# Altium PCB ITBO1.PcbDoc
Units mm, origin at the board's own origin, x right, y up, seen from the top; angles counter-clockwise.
Board outline 85 x 45 mm, 2 copper layers (Top Layer, Bottom Layer); 68 components, 43 nets, 200 pads, 0 vias.
Unrouted connection lines stored in the file: 118.
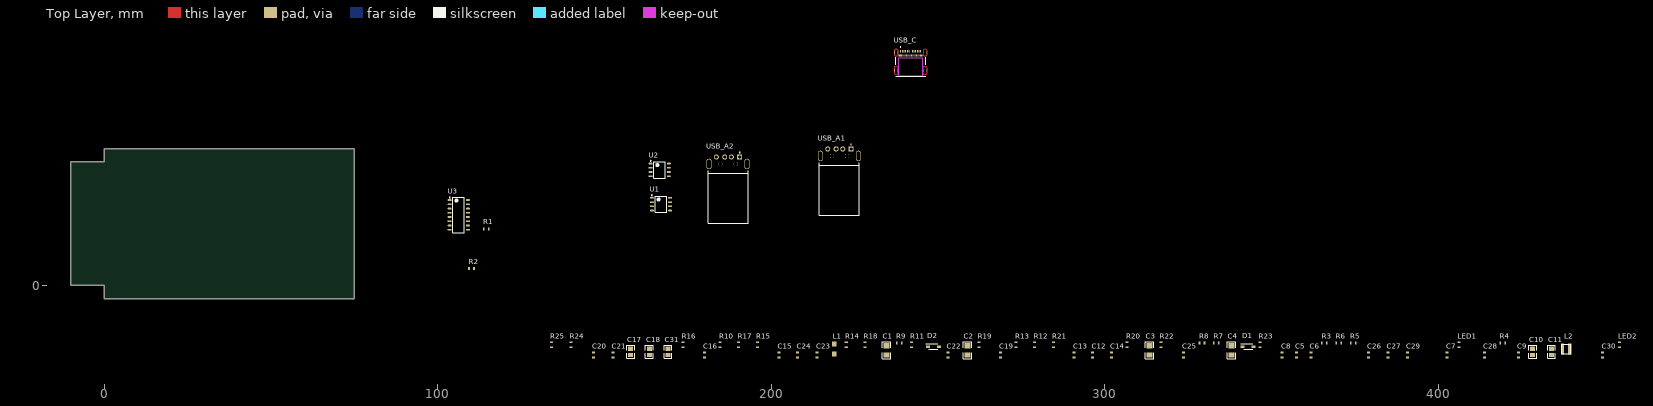
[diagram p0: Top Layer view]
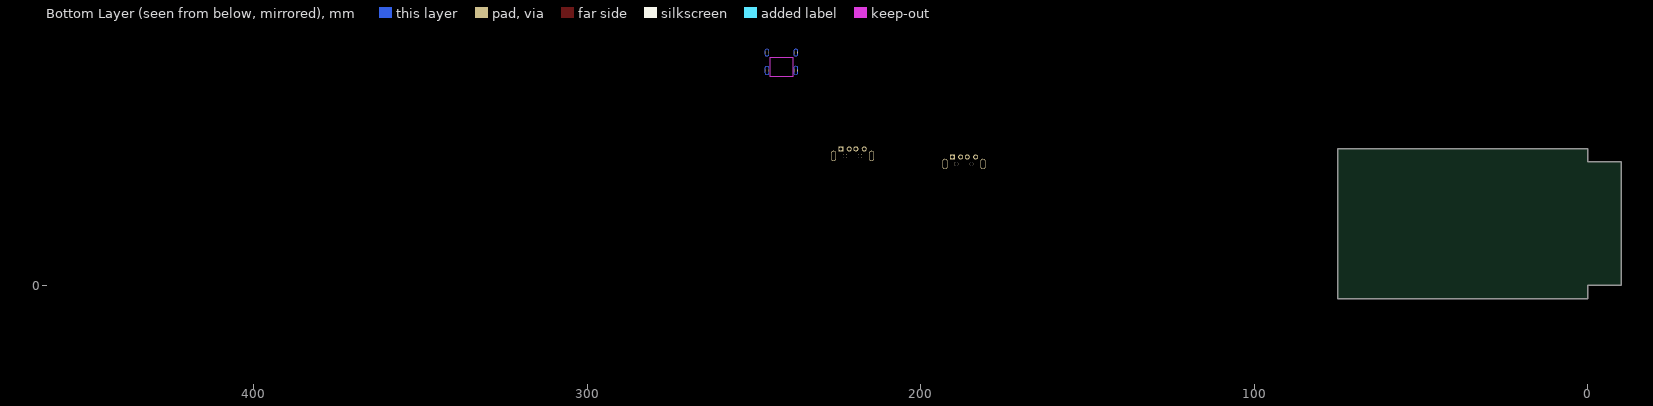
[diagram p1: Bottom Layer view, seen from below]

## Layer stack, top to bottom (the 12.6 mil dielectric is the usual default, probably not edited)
Top Solder: solder mask 0.0102, Solder Resist, Dk 3.5
Top Layer: signal copper 0.0356
Dielectric 1: dielectric 0.32, FR-4, Dk 4.8
Bottom Layer: signal copper 0.0356
Bottom Solder: solder mask 0.0102, Solder Resist, Dk 3.5

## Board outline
0,0 -10,0 -10,37 0,37 0,41 75,41 75,-4 0,-4

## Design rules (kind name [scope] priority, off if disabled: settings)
Clearance [All] p1: gap=0.254 ignorepadtopadclearanceinfootprint=FALSE except(0: Arc-Hole Track-Hole SMDPad-Hole THPad-Hole Via-Hole Fill-Hole Poly-Hole Region-Hole Text-Hole)
PolygonConnect [All] p1: connectstyle=Relief reliefconductorwidth=0.254 reliefentries=4 polygonreliefangle="90 Angle" airgapwidth=0.254
RoomDefinition ITBO1 [InComponentClass('ITBO1')] p1: confinementstyle=ConfineIn formatcopy=TRUE lockcomponents=FALSE outline 125.345,-47.575 459.992,-47.575 459.992,94.03 125.345,94.03
RoutingVias [All] p1: holewidth=0.711 width=1.27 viastyle="Through Hole" minholewidth=0.711 minwidth=1.27 maxholewidth=0.711 maxwidth=1.27
SolderMaskExpansion [All] p1: expansion=0.102 istentingtop=FALSE
Width [All] p1: maxlimit=0.254 minlimit=0.254 preferedwidth=0.254
30 further rules are at their usual default settings.

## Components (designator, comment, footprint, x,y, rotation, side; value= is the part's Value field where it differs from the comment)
C1 "375n" 1206 234.567,-20.88 r90 top
C2 "375n" 1206 258.824,-20.88 r90 top
C3 "375n" 1206 313.434,-20.88 r90 top
C4 "375n" 1206 338.072,-20.88 r90 top
C5 "33u" "0603 - R" 357.503,-20.88 r90 top
C6 "33u" "0603 - R" 361.821,-20.88 r90 top
C7 "" "0603 - R" 402.715,-20.88 r90 top
C8 "11.67u" "0603 - R" 353.185,-20.88 r90 top
C9 "13.83u" "0603 - R" 424.051,-20.88 r90 top
C10 "13.75u" 0805 428.369,-20.88 r90 top
C11 "13.73u" 0805 433.957,-20.88 r90 top
C12 "4.82n" "0603 - R" 296.416,-20.88 r90 top
C13 "1.14n" "0603 - R" 290.828,-20.88 r90 top
C14 "866p" "0603 - R" 302.004,-20.88 r90 top
C15 "9.41n" "0603 - R" 202.309,-20.88 r90 top
C16 "41.84n" "0603 - R" 179.957,-20.88 r90 top
C17 "33u" 0805 157.859,-20.88 r90 top
C18 "33u" 0805 163.447,-20.88 r90 top
C19 "9.65n" "0603 - R" 268.73,-20.88 r90 top
C20 "9.5n" "0603 - R" 146.683,-20.88 r90 top
C21 "734p" "0603 - R" 152.525,-20.88 r90 top
C22 "85n" "0603 - R" 252.982,-20.88 r90 top
C23 "7.67u" "0603 - R" 213.739,-20.88 r90 top
C24 "7.67u" "0603 - R" 207.897,-20.88 r90 top
C25 "0.97n" "0603 - R" 323.594,-20.88 r90 top
C26 "42.38n" "0603 - R" 379.093,-20.88 r90 top
C27 "42.38n" "0603 - R" 384.935,-20.88 r90 top
C28 "9.92n" "0603 - R" 413.891,-20.88 r90 top
C29 "42n" "0603 - R" 390.777,-20.88 r90 top
C30 "7.68u" "0603 - R" 449.324,-20.88 r90 top
C31 "33u" 0805 169.035,-20.88 r90 top
D1 "1N4148W-7-F" DIODES_SOD123_2_H 343.025,-18.34 r0 top
D2 "1N4148W-7-F" DIODES_SOD123_2_H 248.664,-18.34 r0 top
L1 "L" "1806 - R" 218.946,-19.102 r90 top value=6.716u
L2 "10.5u" WE-TPC 438.402,-19.102 r90 top
LED1 "tbd" "LED-RED-0603[1608]  - RFL" 406.271,-17.832 r90 top value=RED
LED2 "tbd" "LED-BLUE-0603[1608]  - RFL" 454.404,-17.832 r90 top value=BLUE
R1 "4.7" "0603 - R" 114.562,16.941 r0 top value=1k
R2 "4.7" "0603 - R" 110.105,5.003 r0 top value=1k
R3 "47k" "0603 - R" 365.885,-17.324 r0 top value=47k5
R4 "110k" "0603 - R" 419.352,-17.324 r0 top
R5 "57k6" "0603 - R" 374.521,-17.324 r0 top
R6 "4.7" "0603 - R" 370.203,-17.324 r0 top
R7 "224k" "0603 - R" 333.5,-17.324 r0 top
R8 "2k22" "0603 - R" 329.182,-17.324 r0 top
R9 "112k" "0603 - R" 238.377,-17.324 r0 top
R10 "112k" "0603 - R" 184.656,-17.832 r90 top
R11 "47.3k" "0603 - R" 242.06,-17.832 r90 top
R12 "4k72" "0603 - R" 279.017,-17.832 r90 top
R13 "33k3" "0603 - R" 273.429,-17.832 r90 top
R14 "2meg7" "0603 - R" 222.502,-17.832 r90 top
R15 "22k3" "0603 - R" 195.832,-17.832 r90 top
R16 "100k" "0603 - R" 173.48,-17.832 r90 top
R17 "22k3" "0603 - R" 190.244,-17.832 r90 top
R18 "1K" "0603 - R" 228.09,-17.832 r90 top
R19 "2k22" "0603 - R" 262.253,-17.832 r90 top
R20 "1K" "0603 - R" 306.703,-17.832 r90 top
R21 "1K" "0603 - R" 284.605,-17.832 r90 top
R22 "7k" "0603 - R" 316.863,-17.832 r90 top
R23 "7k" "0603 - R" 346.581,-17.832 r90 top
R24 "3k32" "0603 - R" 139.952,-17.832 r90 top
R25 "22k3" "0603 - R" 134.11,-17.832 r90 top
U1 "ITBO1_U1" ITBO1_U1 166.934,24.332 r0 top
U2 "ITBO1_U2" ITBO1_U2 166.553,34.619 r0 top
U3 "ITBO1_U3" ITBO1_U3 106.295,21.132 r0 top
USB_A1 "ITBO_USB_A1" MOLEX_48037-0001 220.455,38.81 r0 top
USB_A2 "ITBO_USB_A2" MOLEX_48037-0001 187.054,36.397 r0 top
USB_C "ITBO_USB_C" MOLEX_105450-0101 241.802,66.439 r0 top

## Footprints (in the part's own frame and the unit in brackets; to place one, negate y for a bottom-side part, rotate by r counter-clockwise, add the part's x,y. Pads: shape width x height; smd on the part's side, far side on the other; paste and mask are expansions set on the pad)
"0603 - R" [mm] "SMD Chip 0603 - Reflow"
  rect 0.5x0.9 smd: 1(-0.75,0) 2(0.75,0)
0805 [mm] "SMD Chip 0805"
  rect 1.3x1.5 smd: 1(0,0) 2(1.9,0)
  silkscreen extent -1.05,-1.15 2.95,1.15
1206 [mm] "SMD Chip 1206"
  rect 1.6x1.8 smd: 1(0,0) 2(2.8,0)
  silkscreen extent -1.2,-1.3 4,1.3
"1806 - R" [mm] "Body 5 x 2 mm (LxW typ)"
  rect 1.5x1.35 smd: 1(-1.5,0) 2(1.5,0)
DIODES_SOD123_2_H [mm] "DIODES_SOD123_2_H"
  rect 1.25x0.75 smd: 1(-1.65,0) 2(1.65,0)
  silkscreen extent -2.27,-0.8 1.35,0.8, body extent -1.42,-0.85 1.43,0.85, height 1.35
ITBO1_U1 [mm] "TSOP, 8-Leads, Body 4.85x3.85mm, Pitch 1.27mm, IPC Medium Density"
  oval 1.2x0.5 smd: 1(-2.725,1.905) 2(-2.725,0.635) 3(-2.725,-0.635) 4(-2.725,-1.905) 5(2.725,-1.905) 6(2.725,-0.635) 7(2.725,0.635) 8(2.725,1.905)
  silkscreen extent -2.85,-2.45 1.73,2.83, body extent -2.93,-2.45 2.93,2.45, height 1.25
ITBO1_U2 [mm] "TSOP, 8-Leads, Body 4.85x3.85mm, Pitch 1.27mm, IPC Medium Density"
  oval 1.2x0.5 smd: 1(-2.725,1.905) 2(-2.725,0.635) 3(-2.725,-0.635) 4(-2.725,-1.905) 5(2.725,-1.905) 6(2.725,-0.635) 7(2.725,0.635) 8(2.725,1.905)
  silkscreen extent -2.85,-2.45 1.73,2.83, body extent -2.93,-2.45 2.93,2.45, height 1.25
ITBO1_U3 [mm]
  oval 1.2x0.5 smd: 1(-2.725,4.445) 2(-2.725,3.175) 3(-2.725,1.905) 4(-2.725,0.635) 5(-2.725,-0.635) 6(-2.725,-1.905) 7(-2.725,-3.175) 8(-2.725,-4.445) 9(2.725,-4.445) 10(2.725,-3.175) 11(2.725,-1.905) 12(2.725,-0.635) 13(2.725,0.635) 14(2.725,1.905) 15(2.725,3.175) 16(2.725,4.445)
  silkscreen extent -2.85,-5.3 1.73,5.37, body extent -2.93,-5.3 2.93,5.3, height 1.25
"LED-BLUE-0603[1608]  - RFL" [mm] "SMD Chip 0603 - LED BLUE - RFL"
  rect 0.5x0.9 smd: 1(-0.75,0) 2(0.75,0)
  body extent -0.85,-0.42 0.77,0.38, height 0.6
"LED-RED-0603[1608]  - RFL" [mm] "SMD Chip 0603 - LED RED - RFL"
  rect 0.5x0.9 smd: 1(-0.75,0) 2(0.75,0)
  body extent -0.85,-0.42 0.77,0.38, height 0.6
MOLEX_48037-0001 [mm]
  rect 1.508x1.508 hole 1: 1(3.5,2.1)
  round 1.508 hole 1: 2(1,2.1) 3(-1,2.1) 4(-3.5,2.1)
  oval 1.575x3.15 hole 1.05 slot 2.6 at 90 deg: S1(5.7,0) S2(-5.7,0)
  round 1.25 hole 1.25 unplated: ""(-2.25,0) ""(2.25,0)
  silkscreen extent -6,-17.8 6,3.5
MOLEX_105450-0101 [mm]
  rect 0.3x0.7 smd: A1(-3,3.77) A2(-2.5,3.77) A3(-2,3.77) A4(-1.5,3.77) A5(-1,3.77) A6(-0.5,3.77) A7(0.5,3.77) A8(1,3.77) A9(1.5,3.77) A10(2,3.77) A11(2.5,3.77) A12(3,3.77) B2(2.25,2.47) B3(1.75,2.47) B4(1.25,2.47) B5(0.75,2.47) B6(0.25,2.47) B7(-0.25,2.47) B8(-0.75,2.47) B9(-1.25,2.47) B10(-1.75,2.47) B11(-2.25,2.47)
  rect 1x0.7 smd: B1(3.1,2.47) B12(-3.1,2.47)
  round 1.2 hole 0.65 slot 1.7 at 90 deg mask+0: S1(-4.32,3.36)
  round 1.2 hole 0.65 slot 1.725 at 90 deg mask+0: S2(4.32,3.36)
  round 1.2 hole 0.65 slot 2.175 at 90 deg mask+0: S3(-4.32,-2) S4(4.32,-2)
  Top Layer region: 4.35,-0.702 4.382,-0.706 4.414,-0.711 4.446,-0.718 4.478,-0.727 4.509,-0.737 4.539,-0.749 4.569,-0.763 4.598,-0.778 4.626,-0.795 4.654,-0.813 4.68,-0.832 4.705,-0.853 4.73,-0.875 4.752,-0.898 4.774,-0.923 4.795,-0.949 4.814,-0.975 4.831,-1.003 4.847,-1.031 4.862,-1.061 4.875,-1.091 4.886,-1.121 4.896,-1.153 4.904,-1.184 4.911,-1.216 4.916,-1.249 4.919,-1.281 4.92,-1.314 4.92,-1.35 4.92,-2.65 4.92,-2.686 4.919,-2.719 4.916,-2.751 4.911,-2.784 4.904,-2.816 4.896,-2.847 4.886,-2.879 4.875,-2.909 4.862,-2.939 4.847,-2.969 4.831,-2.997 4.814,-3.025 4.795,-3.051 4.774,-3.077 4.752,-3.102 4.73,-3.125 4.705,-3.147 4.68,-3.168 4.654,-3.187 4.626,-3.205 4.598,-3.222 4.569,-3.237 4.539,-3.251 4.509,-3.263 4.478,-3.273 4.446,-3.282 4.414,-3.289 4.382,-3.294 4.35,-3.298 4.32,-3.3 4.29,-3.298 4.258,-3.294 4.226,-3.289 4.194,-3.282 4.162,-3.273 4.131,-3.263 4.101,-3.251 4.071,-3.237 4.042,-3.222 4.014,-3.205 3.986,-3.187 3.96,-3.168 3.935,-3.147 3.91,-3.125 3.888,-3.102 3.866,-3.077 3.845,-3.051 3.826,-3.025 3.809,-2.997 3.793,-2.969 3.778,-2.939 3.765,-2.909 3.754,-2.879 3.744,-2.847 3.736,-2.816 3.729,-2.784 3.724,-2.751 3.721,-2.719 3.72,-2.686 3.72,-2.65 3.72,-1.35 3.72,-1.314 3.721,-1.281 3.724,-1.249 3.729,-1.216 3.736,-1.184 3.744,-1.153 3.754,-1.121 3.765,-1.091 3.778,-1.061 3.793,-1.031 3.809,-1.003 3.826,-0.975 3.845,-0.949 3.866,-0.923 3.888,-0.898 3.91,-0.875 3.935,-0.853 3.96,-0.832 3.986,-0.813 4.014,-0.795 4.042,-0.778 4.071,-0.763 4.101,-0.749 4.131,-0.737 4.162,-0.727 4.194,-0.718 4.226,-0.711 4.258,-0.706 4.29,-0.702 4.32,-0.7
  Top Layer region: -4.29,-0.652 -4.258,-0.656 -4.226,-0.661 -4.194,-0.668 -4.162,-0.677 -4.131,-0.687 -4.101,-0.699 -4.071,-0.713 -4.042,-0.728 -4.014,-0.745 -3.986,-0.763 -3.96,-0.782 -3.935,-0.803 -3.91,-0.825 -3.888,-0.848 -3.866,-0.873 -3.845,-0.899 -3.826,-0.925 -3.809,-0.953 -3.793,-0.981 -3.778,-1.011 -3.765,-1.041 -3.754,-1.071 -3.744,-1.103 -3.736,-1.134 -3.729,-1.166 -3.724,-1.199 -3.721,-1.231 -3.72,-1.264 -3.72,-1.3 -3.72,-2.7 -3.72,-2.736 -3.721,-2.769 -3.724,-2.801 -3.729,-2.834 -3.736,-2.866 -3.744,-2.897 -3.754,-2.929 -3.765,-2.959 -3.778,-2.989 -3.793,-3.019 -3.809,-3.047 -3.826,-3.075 -3.845,-3.101 -3.866,-3.127 -3.888,-3.152 -3.91,-3.175 -3.935,-3.197 -3.96,-3.218 -3.986,-3.237 -4.014,-3.255 -4.042,-3.272 -4.071,-3.287 -4.101,-3.301 -4.131,-3.313 -4.162,-3.323 -4.194,-3.332 -4.226,-3.339 -4.258,-3.344 -4.29,-3.348 -4.32,-3.35 -4.35,-3.348 -4.382,-3.344 -4.414,-3.339 -4.446,-3.332 -4.478,-3.323 -4.509,-3.313 -4.539,-3.301 -4.569,-3.287 -4.598,-3.272 -4.626,-3.255 -4.654,-3.237 -4.68,-3.218 -4.705,-3.197 -4.73,-3.175 -4.752,-3.152 -4.774,-3.127 -4.795,-3.101 -4.814,-3.075 -4.831,-3.047 -4.847,-3.019 -4.862,-2.989 -4.875,-2.959 -4.886,-2.929 -4.896,-2.897 -4.904,-2.866 -4.911,-2.834 -4.916,-2.801 -4.919,-2.769 -4.92,-2.736 -4.92,-2.7 -4.92,-1.3 -4.92,-1.264 -4.919,-1.231 -4.916,-1.199 -4.911,-1.166 -4.904,-1.134 -4.896,-1.103 -4.886,-1.071 -4.875,-1.041 -4.862,-1.011 -4.847,-0.981 -4.831,-0.953 -4.814,-0.925 -4.795,-0.899 -4.774,-0.873 -4.752,-0.848 -4.73,-0.825 -4.705,-0.803 -4.68,-0.782 -4.654,-0.763 -4.626,-0.745 -4.598,-0.728 -4.569,-0.713 -4.539,-0.699 -4.509,-0.687 -4.478,-0.677 -4.446,-0.668 -4.414,-0.661 -4.382,-0.656 -4.35,-0.652 -4.32,-0.65
  Top Layer region: 4.351,4.459 4.383,4.457 4.414,4.453 4.445,4.447 4.475,4.44 4.505,4.431 4.535,4.42 4.564,4.408 4.592,4.395 4.62,4.38 4.647,4.363 4.673,4.345 4.698,4.326 4.721,4.306 4.744,4.284 4.766,4.261 4.786,4.238 4.805,4.213 4.823,4.187 4.84,4.16 4.855,4.132 4.868,4.104 4.88,4.075 4.891,4.045 4.9,4.015 4.907,3.985 4.913,3.954 4.917,3.923 4.919,3.891 4.92,3.86 4.92,2.86 4.919,2.829 4.917,2.797 4.913,2.766 4.907,2.735 4.9,2.705 4.891,2.675 4.88,2.645 4.868,2.616 4.855,2.588 4.84,2.56 4.823,2.533 4.805,2.507 4.786,2.482 4.766,2.459 4.744,2.436 4.721,2.414 4.698,2.394 4.673,2.375 4.647,2.357 4.62,2.34 4.592,2.325 4.564,2.312 4.535,2.3 4.505,2.289 4.475,2.28 4.445,2.273 4.414,2.267 4.383,2.263 4.351,2.261 4.32,2.26 4.289,2.261 4.257,2.263 4.226,2.267 4.195,2.273 4.165,2.28 4.135,2.289 4.105,2.3 4.076,2.312 4.048,2.325 4.02,2.34 3.993,2.357 3.967,2.375 3.942,2.394 3.919,2.414 3.896,2.436 3.874,2.459 3.854,2.482 3.835,2.507 3.817,2.533 3.8,2.56 3.785,2.588 3.772,2.616 3.76,2.645 3.749,2.675 3.74,2.705 3.733,2.735 3.727,2.766 3.723,2.797 3.721,2.829 3.72,2.86 3.72,3.86 3.721,3.891 3.723,3.923 3.727,3.954 3.733,3.985 3.74,4.015 3.749,4.045 3.76,4.075 3.772,4.104 3.785,4.132 3.8,4.16 3.817,4.187 3.835,4.213 3.854,4.238 3.874,4.261 3.896,4.284 3.919,4.306 3.942,4.326 3.967,4.345 3.993,4.363 4.02,4.38 4.048,4.395 4.076,4.408 4.105,4.42 4.135,4.431 4.165,4.44 4.195,4.447 4.226,4.453 4.257,4.457 4.289,4.459 4.32,4.46
  Top Layer region: -4.289,4.459 -4.257,4.457 -4.226,4.453 -4.195,4.447 -4.165,4.44 -4.135,4.431 -4.105,4.42 -4.076,4.408 -4.048,4.395 -4.02,4.38 -3.993,4.363 -3.967,4.345 -3.942,4.326 -3.919,4.306 -3.896,4.284 -3.874,4.261 -3.854,4.238 -3.835,4.213 -3.817,4.187 -3.8,4.16 -3.785,4.132 -3.772,4.104 -3.76,4.075 -3.749,4.045 -3.74,4.015 -3.733,3.985 -3.727,3.954 -3.723,3.923 -3.721,3.891 -3.72,3.86 -3.72,2.86 -3.721,2.829 -3.723,2.797 -3.727,2.766 -3.733,2.735 -3.74,2.705 -3.749,2.675 -3.76,2.645 -3.772,2.616 -3.785,2.588 -3.8,2.56 -3.817,2.533 -3.835,2.507 -3.854,2.482 -3.874,2.459 -3.896,2.436 -3.919,2.414 -3.942,2.394 -3.967,2.375 -3.993,2.357 -4.02,2.34 -4.048,2.325 -4.076,2.312 -4.105,2.3 -4.135,2.289 -4.165,2.28 -4.195,2.273 -4.226,2.267 -4.257,2.263 -4.289,2.261 -4.32,2.26 -4.355,2.26 -4.385,2.261 -4.415,2.264 -4.445,2.268 -4.474,2.274 -4.504,2.282 -4.532,2.291 -4.561,2.301 -4.588,2.313 -4.615,2.327 -4.641,2.342 -4.667,2.358 -4.691,2.375 -4.715,2.394 -4.738,2.414 -4.759,2.435 -4.779,2.457 -4.799,2.481 -4.816,2.505 -4.833,2.53 -4.848,2.556 -4.862,2.583 -4.875,2.61 -4.886,2.638 -4.895,2.667 -4.903,2.696 -4.91,2.725 -4.915,2.755 -4.918,2.785 -4.92,2.81 -4.92,3.81 -4.92,3.846 -4.919,3.879 -4.916,3.911 -4.911,3.944 -4.904,3.976 -4.896,4.007 -4.886,4.039 -4.875,4.069 -4.862,4.099 -4.847,4.129 -4.831,4.157 -4.814,4.185 -4.795,4.211 -4.774,4.237 -4.752,4.262 -4.73,4.285 -4.705,4.307 -4.68,4.328 -4.654,4.347 -4.626,4.365 -4.598,4.382 -4.569,4.397 -4.539,4.411 -4.509,4.423 -4.478,4.433 -4.446,4.442 -4.414,4.449 -4.382,4.454 -4.35,4.458 -4.32,4.46
  Bottom Layer region: 4.35,-0.702 4.382,-0.706 4.414,-0.711 4.446,-0.718 4.478,-0.727 4.509,-0.737 4.539,-0.749 4.569,-0.763 4.598,-0.778 4.626,-0.795 4.654,-0.813 4.68,-0.832 4.705,-0.853 4.73,-0.875 4.752,-0.898 4.774,-0.923 4.795,-0.949 4.814,-0.975 4.831,-1.003 4.847,-1.031 4.862,-1.061 4.875,-1.091 4.886,-1.121 4.896,-1.153 4.904,-1.184 4.911,-1.216 4.916,-1.249 4.919,-1.281 4.92,-1.314 4.92,-1.35 4.92,-2.65 4.92,-2.686 4.919,-2.719 4.916,-2.751 4.911,-2.784 4.904,-2.816 4.896,-2.847 4.886,-2.879 4.875,-2.909 4.862,-2.939 4.847,-2.969 4.831,-2.997 4.814,-3.025 4.795,-3.051 4.774,-3.077 4.752,-3.102 4.73,-3.125 4.705,-3.147 4.68,-3.168 4.654,-3.187 4.626,-3.205 4.598,-3.222 4.569,-3.237 4.539,-3.251 4.509,-3.263 4.478,-3.273 4.446,-3.282 4.414,-3.289 4.382,-3.294 4.35,-3.298 4.32,-3.3 4.29,-3.298 4.258,-3.294 4.226,-3.289 4.194,-3.282 4.162,-3.273 4.131,-3.263 4.101,-3.251 4.071,-3.237 4.042,-3.222 4.014,-3.205 3.986,-3.187 3.96,-3.168 3.935,-3.147 3.91,-3.125 3.888,-3.102 3.866,-3.077 3.845,-3.051 3.826,-3.025 3.809,-2.997 3.793,-2.969 3.778,-2.939 3.765,-2.909 3.754,-2.879 3.744,-2.847 3.736,-2.816 3.729,-2.784 3.724,-2.751 3.721,-2.719 3.72,-2.686 3.72,-2.65 3.72,-1.35 3.72,-1.314 3.721,-1.281 3.724,-1.249 3.729,-1.216 3.736,-1.184 3.744,-1.153 3.754,-1.121 3.765,-1.091 3.778,-1.061 3.793,-1.031 3.809,-1.003 3.826,-0.975 3.845,-0.949 3.866,-0.923 3.888,-0.898 3.91,-0.875 3.935,-0.853 3.96,-0.832 3.986,-0.813 4.014,-0.795 4.042,-0.778 4.071,-0.763 4.101,-0.749 4.131,-0.737 4.162,-0.727 4.194,-0.718 4.226,-0.711 4.258,-0.706 4.29,-0.702 4.32,-0.7
  Bottom Layer region: -4.29,-0.652 -4.258,-0.656 -4.226,-0.661 -4.194,-0.668 -4.162,-0.677 -4.131,-0.687 -4.101,-0.699 -4.071,-0.713 -4.042,-0.728 -4.014,-0.745 -3.986,-0.763 -3.96,-0.782 -3.935,-0.803 -3.91,-0.825 -3.888,-0.848 -3.866,-0.873 -3.845,-0.899 -3.826,-0.925 -3.809,-0.953 -3.793,-0.981 -3.778,-1.011 -3.765,-1.041 -3.754,-1.071 -3.744,-1.103 -3.736,-1.134 -3.729,-1.166 -3.724,-1.199 -3.721,-1.231 -3.72,-1.264 -3.72,-1.3 -3.72,-2.7 -3.72,-2.736 -3.721,-2.769 -3.724,-2.801 -3.729,-2.834 -3.736,-2.866 -3.744,-2.897 -3.754,-2.929 -3.765,-2.959 -3.778,-2.989 -3.793,-3.019 -3.809,-3.047 -3.826,-3.075 -3.845,-3.101 -3.866,-3.127 -3.888,-3.152 -3.91,-3.175 -3.935,-3.197 -3.96,-3.218 -3.986,-3.237 -4.014,-3.255 -4.042,-3.272 -4.071,-3.287 -4.101,-3.301 -4.131,-3.313 -4.162,-3.323 -4.194,-3.332 -4.226,-3.339 -4.258,-3.344 -4.29,-3.348 -4.32,-3.35 -4.35,-3.348 -4.382,-3.344 -4.414,-3.339 -4.446,-3.332 -4.478,-3.323 -4.509,-3.313 -4.539,-3.301 -4.569,-3.287 -4.598,-3.272 -4.626,-3.255 -4.654,-3.237 -4.68,-3.218 -4.705,-3.197 -4.73,-3.175 -4.752,-3.152 -4.774,-3.127 -4.795,-3.101 -4.814,-3.075 -4.831,-3.047 -4.847,-3.019 -4.862,-2.989 -4.875,-2.959 -4.886,-2.929 -4.896,-2.897 -4.904,-2.866 -4.911,-2.834 -4.916,-2.801 -4.919,-2.769 -4.92,-2.736 -4.92,-2.7 -4.92,-1.3 -4.92,-1.264 -4.919,-1.231 -4.916,-1.199 -4.911,-1.166 -4.904,-1.134 -4.896,-1.103 -4.886,-1.071 -4.875,-1.041 -4.862,-1.011 -4.847,-0.981 -4.831,-0.953 -4.814,-0.925 -4.795,-0.899 -4.774,-0.873 -4.752,-0.848 -4.73,-0.825 -4.705,-0.803 -4.68,-0.782 -4.654,-0.763 -4.626,-0.745 -4.598,-0.728 -4.569,-0.713 -4.539,-0.699 -4.509,-0.687 -4.478,-0.677 -4.446,-0.668 -4.414,-0.661 -4.382,-0.656 -4.35,-0.652 -4.32,-0.65
  Bottom Layer region: 4.351,4.459 4.383,4.457 4.414,4.453 4.445,4.447 4.475,4.44 4.505,4.431 4.535,4.42 4.564,4.408 4.592,4.395 4.62,4.38 4.647,4.363 4.673,4.345 4.698,4.326 4.721,4.306 4.744,4.284 4.766,4.261 4.786,4.238 4.805,4.213 4.823,4.187 4.84,4.16 4.855,4.132 4.868,4.104 4.88,4.075 4.891,4.045 4.9,4.015 4.907,3.985 4.913,3.954 4.917,3.923 4.919,3.891 4.92,3.86 4.92,2.86 4.919,2.829 4.917,2.797 4.913,2.766 4.907,2.735 4.9,2.705 4.891,2.675 4.88,2.645 4.868,2.616 4.855,2.588 4.84,2.56 4.823,2.533 4.805,2.507 4.786,2.482 4.766,2.459 4.744,2.436 4.721,2.414 4.698,2.394 4.673,2.375 4.647,2.357 4.62,2.34 4.592,2.325 4.564,2.312 4.535,2.3 4.505,2.289 4.475,2.28 4.445,2.273 4.414,2.267 4.383,2.263 4.351,2.261 4.32,2.26 4.289,2.261 4.257,2.263 4.226,2.267 4.195,2.273 4.165,2.28 4.135,2.289 4.105,2.3 4.076,2.312 4.048,2.325 4.02,2.34 3.993,2.357 3.967,2.375 3.942,2.394 3.919,2.414 3.896,2.436 3.874,2.459 3.854,2.482 3.835,2.507 3.817,2.533 3.8,2.56 3.785,2.588 3.772,2.616 3.76,2.645 3.749,2.675 3.74,2.705 3.733,2.735 3.727,2.766 3.723,2.797 3.721,2.829 3.72,2.86 3.72,3.86 3.721,3.891 3.723,3.923 3.727,3.954 3.733,3.985 3.74,4.015 3.749,4.045 3.76,4.075 3.772,4.104 3.785,4.132 3.8,4.16 3.817,4.187 3.835,4.213 3.854,4.238 3.874,4.261 3.896,4.284 3.919,4.306 3.942,4.326 3.967,4.345 3.993,4.363 4.02,4.38 4.048,4.395 4.076,4.408 4.105,4.42 4.135,4.431 4.165,4.44 4.195,4.447 4.226,4.453 4.257,4.457 4.289,4.459 4.32,4.46
  Bottom Layer region: -4.289,4.459 -4.257,4.457 -4.226,4.453 -4.195,4.447 -4.165,4.44 -4.135,4.431 -4.105,4.42 -4.076,4.408 -4.048,4.395 -4.02,4.38 -3.993,4.363 -3.967,4.345 -3.942,4.326 -3.919,4.306 -3.896,4.284 -3.874,4.261 -3.854,4.238 -3.835,4.213 -3.817,4.187 -3.8,4.16 -3.785,4.132 -3.772,4.104 -3.76,4.075 -3.749,4.045 -3.74,4.015 -3.733,3.985 -3.727,3.954 -3.723,3.923 -3.721,3.891 -3.72,3.86 -3.72,2.86 -3.721,2.829 -3.723,2.797 -3.727,2.766 -3.733,2.735 -3.74,2.705 -3.749,2.675 -3.76,2.645 -3.772,2.616 -3.785,2.588 -3.8,2.56 -3.817,2.533 -3.835,2.507 -3.854,2.482 -3.874,2.459 -3.896,2.436 -3.919,2.414 -3.942,2.394 -3.967,2.375 -3.993,2.357 -4.02,2.34 -4.048,2.325 -4.076,2.312 -4.105,2.3 -4.135,2.289 -4.165,2.28 -4.195,2.273 -4.226,2.267 -4.257,2.263 -4.289,2.261 -4.32,2.26 -4.355,2.26 -4.385,2.261 -4.415,2.264 -4.445,2.268 -4.474,2.274 -4.504,2.282 -4.532,2.291 -4.561,2.301 -4.588,2.313 -4.615,2.327 -4.641,2.342 -4.667,2.358 -4.691,2.375 -4.715,2.394 -4.738,2.414 -4.759,2.435 -4.779,2.457 -4.799,2.481 -4.816,2.505 -4.833,2.53 -4.848,2.556 -4.862,2.583 -4.875,2.61 -4.886,2.638 -4.895,2.667 -4.903,2.696 -4.91,2.725 -4.915,2.755 -4.918,2.785 -4.92,2.81 -4.92,3.81 -4.92,3.846 -4.919,3.879 -4.916,3.911 -4.911,3.944 -4.904,3.976 -4.896,4.007 -4.886,4.039 -4.875,4.069 -4.862,4.099 -4.847,4.129 -4.831,4.157 -4.814,4.185 -4.795,4.211 -4.774,4.237 -4.752,4.262 -4.73,4.285 -4.705,4.307 -4.68,4.328 -4.654,4.347 -4.626,4.365 -4.598,4.382 -4.569,4.397 -4.539,4.411 -4.509,4.423 -4.478,4.433 -4.446,4.442 -4.414,4.449 -4.382,4.454 -4.35,4.458 -4.32,4.46
  Keep-Out Layer region: 3.5,-3.77 -3.5,-3.77 -3.5,1.88 3.5,1.88
  silkscreen extent -4.47,-3.77 4.47,5.18
WE-TPC [mm] "Power-Choke WE-TPC 2.8 x 2.8"
  rect 3.2x1 smd: 1(0,1.1) 2(0,-1.1)
  silkscreen extent -1.4,-1.4 1.4,1.4

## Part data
C1 C2 C3 C4 C5 C6 C7 C8 C9 C10 C11 C12 C13 C14 C15 C16 C17 C18 C19 C20 C21 C22 C23 C24 C25 C26 C27 C28 C29 C30 C31: library part C, "Capacitor", #Manufacturer="Generic Components", Initial Voltage=0V
D1 D2: library part 10707_EuR1_Team06-0009-A.1, "Fast Switching Diode, 100 V, 2 A, 300 mA", Manufacturer="Diodes Incorporated"
L1: "Inductor", #Manufacturer="Generic Components"
L2: library part "L - Power", "Inductor - Power", #Manufacturer="Generic Components"
LED1: library part GENERIC-LED-0001-A.7, "LED red", Manufacturer=generic
LED2: library part GENERIC-LED-0005-A.2, "LED blue", Manufacturer=generic
R1 R2 R3 R4 R5 R6 R7 R8 R9 R10 R11 R12 R13 R14 R15 R16 R17 R18 R19 R20 R21 R22 R23 R24 R25: library part R, "Resistor", #Manufacturer="Generic Components"

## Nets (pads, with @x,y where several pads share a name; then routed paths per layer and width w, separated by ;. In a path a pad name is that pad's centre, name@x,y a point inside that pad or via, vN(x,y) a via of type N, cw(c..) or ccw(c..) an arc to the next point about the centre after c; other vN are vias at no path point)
GND: C5.1 C6.1 C8.1 C13.1 C14.1 C17.1 C18.1 C19.2 C20.1 C21.1 C22.2 C23.1 C24.1 C26.1 C27.1 C30.1 C31.1 LED1.1 LED2.1 R3.1 R5.1 R10.1 R12.2 R19.2 R21.2 R24.1 U1.2 U3.12 USB_A1.1 USB_A2.1
NetC1_1: C1.1 C2.1 C3.1 C4.1 R8.1
NetC1_2: C1.2 C2.2 C3.2 C4.2 C26.2 C28.1 C29.2 L1.2 U2.4
NetC5_2: C5.2 C6.2 R13.2 U1.4
NetC7_1: C7.1 R4.1 R5.2 U1.1
NetC8_2: C8.2 R6.1
NetC9_1: C9.1 C10.1 C11.1 U1.7 U1.8
NetC12_1: C12.1 R9.1 R10.2 R17.2
NetC12_2: C12.2 C13.2 D1.1 R7.2
NetC14_2: C14.2 R7.1 R11.2 U3.2
NetC15_1: C15.1 C16.1 L1.1
NetC15_2: C15.2 U2.6
NetC16_2: C16.2 C17.2 C18.2 C29.1 C31.2 U2.7
NetC19_1: C19.1 R12.1 R13.1 U3.1
NetC20_2: C20.2 R16.1
NetC21_2: C21.2 R15.1 R16.2 R17.1
NetC22_1: C22.1 R19.1 U3.4
NetC23_2: C23.2 C24.2 U3.5
NetC25_1: C25.1 R22.2
NetC25_2: C25.2 R23.1 U3.11
NetC27_2: C27.2 U2.5
NetC28_2: C28.2 U2.3
NetC30_2: C30.2 U2.8
NetD1_2: D1.2 R8.2
NetD2_1: D2.1 R20.1 R21.1
NetD2_2: D2.2 R25.1 U3.13
NetL2_1: L2.1 R6.2 U1.5 U1.6
NetLED1_2: LED1.2 R2.2
NetLED2_2: LED2.2 R1.2
"NetMicro USB_4": R24.2 R25.2
NetR1_1: R1.1 U3.14
NetR2_1: R2.1 U3.16
NetR3_2: R3.2 U1.3
NetR9_2: R9.2 R11.1
NetR14_1: R14.1 R18.2 U3.6
NetR14_2: R14.2 R15.2 U3.8
NetR18_1: R18.1 U3.10
NetR20_2: R20.2 R22.1 R23.2
NetU2_1: U2.1 U3.15
NetU2_2: U2.2 U3.9
NetUSB_A1_2: USB_A1.2 USB_A1.3
NetUSB_A2_2: USB_A2.2 USB_A2.3
VCC: C7.2 C9.2 C10.2 C11.2 R4.2 USB_A1.4 USB_A2.4
pads on no net: L2.2 U3.3 U3.7 USB_A1. USB_A1.S1 USB_A1.S2 USB_A2. USB_A2.S1 USB_A2.S2 USB_C.A1 USB_C.A2 USB_C.A3 USB_C.A4 USB_C.A5 USB_C.A6 USB_C.A7 USB_C.A8 USB_C.A9 USB_C.A10 USB_C.A11 USB_C.A12 USB_C.B1 USB_C.B2 USB_C.B3 USB_C.B4 USB_C.B5 USB_C.B6 USB_C.B7 USB_C.B8 USB_C.B9 USB_C.B10 USB_C.B11 USB_C.B12 USB_C.S1 USB_C.S2 USB_C.S3 USB_C.S4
